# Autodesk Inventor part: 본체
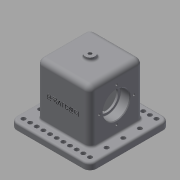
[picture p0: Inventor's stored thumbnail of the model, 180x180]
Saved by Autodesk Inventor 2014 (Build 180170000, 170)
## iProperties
Created: 2018-11
Part Number: 본체
Material: Generic
Document SubType Name: Modeling
Designer: kh
Density: 1 g/cm^3
Appearance: Default
Author: kh
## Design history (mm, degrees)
sketch "스케치1"
  geometry: L1 (60, 60)-(-60, 60); L2 (-60, 60)-(-60, -60); L3 (-60, -60)-(60, -60); L4 (60, -60)-(60, 60); L5 (60, 60)-(-60, -60); L6 (-60, 60)-(60, -60); 1 further point
  constraints: 12 end point, 2 midpoint, 2 parallel, 1 horizontal, 1 perpendicular
  dimensions: "d0" = 120 distance of L3.end L2.end; "d1" = 120 distance of L2.end L1.end
extrude "돌출1" new body sketch "스케치1" distance "d2" = 10; taper "d3" = 0 deg
sketch "스케치2"
  geometry: L1 (-40, -40)-(40, -40); L2 (40, -40)-(40, 40); L3 (40, 40)-(-40, 40); L4 (-40, 40)-(-40, -40); L5 (-40, -40)-(40, 40); L6 (40, -40)-(-40, 40); 1 further point
  constraints: 12 end point, 2 midpoint, 2 parallel, 1 horizontal, 1 perpendicular
  dimensions: "d4" = 80 distance of L3.end L2.end; "d5" = 80 distance of L2.end L1.end
extrude "돌출2" join sketch "스케치2" distance "d6" = 80; taper "d7" = 0 deg
sketch "스케치3"
  geometry: L1 (-23, -30)-(23, -30); L2 (23, -30)-(23, 30); L3 (23, 30)-(-23, 30); L4 (-23, 30)-(-23, -30); L5 (-23, -30)-(23, 30); L6 (23, -30)-(-23, 30); 1 further point
  constraints: 12 end point, 2 midpoint, 2 parallel, 1 horizontal, 1 perpendicular
  dimensions: "d8" = 46 distance of L3.end L2.end; "d9" = 60 distance of L2.end L1.end
extrude "돌출3" cut sketch "스케치3" distance "d10" = 80; taper "d11" = 0 deg
sketch "스케치4"
  geometry: L1 (23, 0)-(-23, 0) reference; L2 (-23, 0)-(23, 0) reference; L3 (-60, 0)-(60, 0) reference; L4 (60, 0)-(-60, 0) reference; L5 (-40, 90)-(40, 90) reference; L6 (40, 90)-(-40, 90) reference; L7 (-40, 48)-(40, 48); L8 (40, 68)-(26, 68); L9 (26, 68)-(26, 64.5); L10 (23, 0)-(23, 80) reference; L11 (23, 0)-(23, 80) reference; L12 (26, 64.5)-(23, 64.5); L13 (40, 68)-(40, 48); L14 (23, 64.5)-(23, 48); 1 further point
  constraints: 12 end point, 3 perpendicular, 3 point on line, 2 parallel
  dimensions: "d12" = 48 distance between parallel lines of L1 L7; "d13" = 33 diameter of L12 L7; "d14" = 40 diameter of L8 L7; "d15" = 14 distance of L8.start L8.end; "d16" = 3 distance of L9.end L12.end
revolve "회전1" sketch "스케치4" stored, may be unused: angle "d17" = 90 deg
node "작업 평면1"
sketch "스케치5"
  geometry: C1 r 7.5 at (0, 0); 2 further points
  constraints: 2 coincident, 1 centre point
  dimensions: "d19" = 15 diameter of C1
extrude "돌출4" join sketch "스케치5" stored distance "d20" = 80; taper "d21" = 0 deg
hole "구멍1" diameter "d24" = 4.917; stored, may be unused: countersink angle "d28" = 90 deg, drill point angle "d30" = 118 deg; dims "d25" = 20, "d26" = 4, "d27" = 2, "d29" = 8, "d71" = 10, "d72" = 10
sketch "스케치6"
  geometry: L1 (40, 64)-(40, 12); L2 (66, 38)-(14, 38); C1 r 20 at (40, 38) reference; A1 r 26 centre (40, 38) between (40, 64) and (40, 12); 7 further points
  constraints: 7 coincident, 4 end point, 4 point on circle, 2 midpoint, 1 centre point, 1 perpendicular, 1 vertical
  dimensions: "d31" = 52 diameter of A1
hole "구멍2" sketch "스케치6" at (40, 64), (14, 38), (40, 12), (66, 38) diameter "d32" = 3.242; stored, may be unused: countersink angle "d36" = 90 deg, drill point angle "d38" = 118 deg; dims "d33" = 8, "d34" = 4, "d35" = 2, "d37" = 10
fillet "모깎기1" dims "d39" = 10
sketch "스케치7"
  geometry: C1 r 3.3 at (50, -50); C2 r 3.3 at (-50, 50); A1 r 10 centre (50, -50) between (50, -60) and (60, -50) reference; A2 r 10 centre (-50, 50) between (-50, 60) and (-60, 50) reference; 1 further point
  constraints: 2 centre point, 2 coincident
  dimensions: "d40" = 6.6 diameter of C1; "d52" = 6.6 diameter of C2
extrude "돌출5" cut sketch "스케치7" stored distance "d41" = 80; taper "d42" = 0 deg
extrude "돌출6" cut sketch "스케치7" stored distance "d53" = 80; taper "d54" = 0 deg
fillet "모깎기2" dims "d61" = 8
fillet "모깎기3" dims "d62" = 0.6
chamfer "모따기1" distance "d63" = 1; stored, may be unused: second distance "d64" = 2, angle "d65" = 45 deg
fillet "모깎기5" dims "d67" = 3
node "작업 평면3"
fillet "모깎기6" dims "d73" = 8
fillet "모깎기7" dims "d74" = 3
sketch "스케치8"
  geometry: L1 (7.308, -27.022)-(56.692, -27.022); L2 (56.692, -27.022)-(56.692, -50.978); L3 (56.692, -50.978)-(7.308, -50.978); L4 (7.308, -50.978)-(7.308, -27.022); L5 (56.692, -27.022)-(7.308, -50.978); L6 (85.3, -87)-(78.7, -87) reference; L7 (75.3, -87)-(68.7, -87) reference; L8 (65.3, -87)-(58.7, -87) reference; L9 (55.3, -87)-(48.7, -87) reference; L10 (45.3, -87)-(38.7, -87) reference; L11 (35.3, -87)-(28.7, -87) reference; L12 (25.3, -87)-(18.7, -87) reference; L13 (15.3, -87)-(8.7, -87) reference; L14 (5.3, -87)-(-1.3, -87) reference; L15 (-4.7, -87)-(-11.3, -87) reference; L16 (-14.7, -87)-(-21.3, -87) reference; L17 (-14.7, -87)-(-21.3, -87) reference; L18 (-14.7, -87)-(-21.3, -87) reference; L19 (-14.7, -87)-(-21.3, -87) reference; L20 (85.3, -87)-(78.7, -87) reference; L21 (85.3, -87)-(78.7, -87) reference; L22 (85.3, -87)-(78.7, -87) reference; L23 (-14.7, -87)-(-21.3, -87) reference; L24 (-4.7, -87)-(-11.3, -87) reference; L25 (5.3, -87)-(-1.3, -87) reference; L26 (15.3, -87)-(8.7, -87) reference; L27 (25.3, -87)-(18.7, -87) reference; L28 (35.3, -87)-(28.7, -87) reference; L29 (45.3, -87)-(38.7, -87) reference; L30 (55.3, -87)-(48.7, -87) reference; L31 (65.3, -87)-(58.7, -87) reference; L32 (75.3, -87)-(68.7, -87) reference; L33 (85.3, -87)-(78.7, -87) reference; L34 (-18, -87)-(-28, -87) reference; L35 (82, -87)-(-18, -87) reference; L36 (92, -87)-(82, -87) reference; L37 (82, -87)-(92, -87) reference; L38 (-18, -87)-(82, -87) reference; L39 (-28, -87)-(-18, -87) reference; L40 (52, -87)-(55, -87) reference; L41 (52, -87)-(12, -87) reference; L42 (9, -87)-(12, -87) reference; L43 (12, -87)-(9, -87) reference; L44 (12, -87)-(52, -87) reference; L45 (55, -87)-(52, -87) reference; L46 (32, -87)-(32, -39)
  constraints: 4 end point, 2 midpoint, 2 other
  dimensions: "d75" = 48 distance of L46.start L46.end
feature "엠보싱1" sketch "스케치8" dims "d0" = 120, "d1" = 120, "d69" = 0.5, "d70" = 0
fillet "모깎기8" dims "d76" = 3
node "솔리드1"
mirror "대칭1"
mirror "대칭2"
pattern_linear "직사각형 패턴1" dims "d45" = 10, "d48" = 25
pattern_linear "직사각형 패턴2" dims "d51" = 25
pattern_linear "직사각형 패턴3" dims "d57" = 25
pattern_linear "직사각형 패턴4" dims "d60" = 10
node "투영된 루프1"
node "투영된 루프2"
node "투영된 루프3"
node "투영된 루프4"
other parameters: "d18" = 5
